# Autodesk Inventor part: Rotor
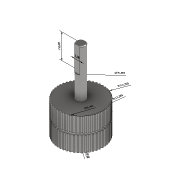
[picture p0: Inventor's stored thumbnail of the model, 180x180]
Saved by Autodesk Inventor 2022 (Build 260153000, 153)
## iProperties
Created: 2020-10
Part Number: Rotor
Material: Generico
Document SubType Name: Modeling
Designer: admin
Density: 1 g/cm^3
Appearance: Acciaio - Lucido
Sending System: SolidWorks 2020
Last Author: Simon
Last Saved: 2020-10-29
Author: admin
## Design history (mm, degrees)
node "Annotazioni"
  node "Quota lineare 2" dims "d3" = 14 (derived)
  node "Quota lineare 3" dims "d6" = 3 (derived)
  node "Quota radiale 1" dims "d10" = 12.5 (derived)
  node "Quota radiale 2" dims "d16" = 0.49084 (derived)
  node "Quota radiale 3" dims "d20" = 12 (derived)
  node "Quota diametro 2" dims "d25" = 5 (derived)
  node "Quota diametro 3" dims "d29" = 5 (derived)
  node "Quota diametro 4" dims "d31" = 4 (derived)
  node "Quota diametro 5" dims "d33" = 0.98168 (derived)
  node "Quota lineare 7" dims "d34" = 0.58899 (derived)
combine "Combine1"
node "Solido1"
other parameters: "d1" = 4.99226 (derived), "d15" = 59.02501 (derived), "d17" = 1.17913 (derived), "d18" = 6.28884 (derived), "d19" = 0.58662 (derived), "d2" = 3.03555 (derived), "d24" = 9.61286 (derived), "d26" = 53.55979 (derived), "d27" = 5.73736 (derived), "d28" = 9.22901 (derived), "d30" = 29.71022 (derived), "d32" = 49.44081 (derived), "d4" = 6.3166 (derived), "d5" = 6.20751 (derived), "d9" = 28.03871 (derived)
